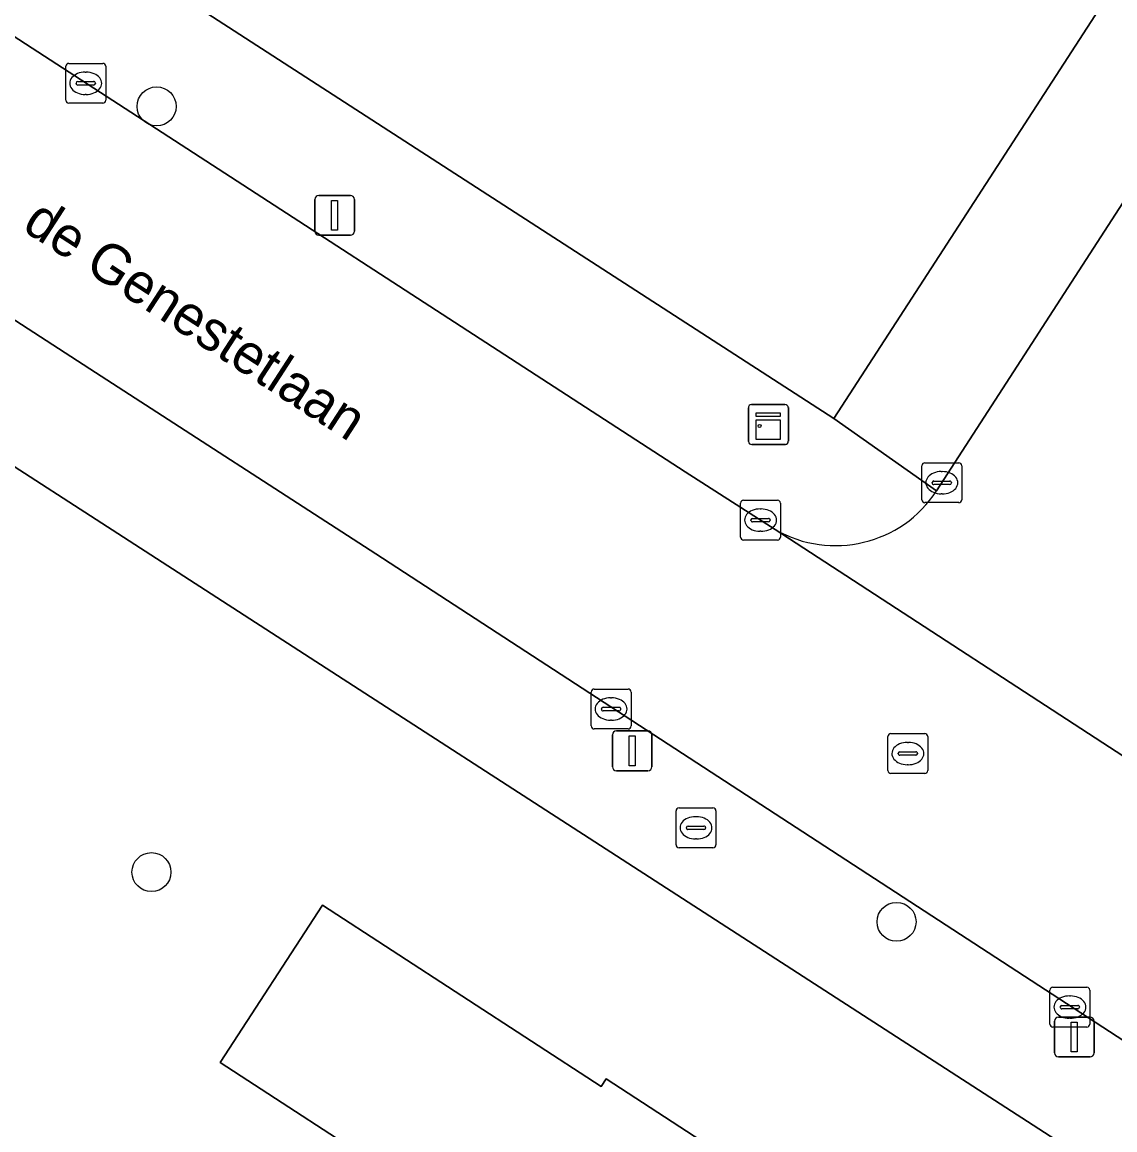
# Model space of a CAD drawing. Extents: x 161139 to 161601, y 381708 to 382245.
# Drawn here: x 161442.02 to 161469.43, y 381969.93 to 381997.72 of the extents above; entities that cross this region are included whole.
import ezdxf

# ---------------------------------------------------------------- set-up
doc = ezdxf.new("R2010")
doc.units = 0
for name, color, linetype in [('IMGEO_Boom', 7, 'Continuous'), ('IMGEO_Brandkraan', 7, 'Continuous'), ('IMGEO_Erf', 7, 'Continuous'), ('IMGEO_Kast', 7, 'Continuous'), ('IMGEO_Kolk', 7, 'Continuous'), ('IMGEO_Lichtmast', 7, 'Continuous'), ('IMGEO_Openbare_ruimte_label', 7, 'Continuous'), ('IMGEO_Pand', 7, 'Continuous'), ('IMGEO_Rijbaan_lokaal_open', 7, 'Continuous'), ('IMGEO_Rioolput', 7, 'Continuous'), ('IMGEO_Voetpad_open', 7, 'Continuous')]:
    doc.layers.add(name, color=color, linetype=linetype)

msp = doc.modelspace()

# ---------------------------------------------------------------- linework, layer by layer
at = {"layer": 'IMGEO_Boom'}
for centre in [(161445.391, 381995.605), (161445.263, 381976.392), (161463.951, 381975.145)]:
    msp.add_circle(centre, 0.489, dxfattribs=at)
at = {"layer": 'IMGEO_Brandkraan'}
for p, q in [((161458.42, 381977.078), (161458.42, 381977.93)), ((161458.495, 381978.004), (161459.347, 381978.004)), ((161459.421, 381977.93), (161459.421, 381977.078)), ((161458.908, 381977.784), (161458.933, 381977.784)), ((161458.679, 381977.498), (161458.679, 381977.51)), ((161459.117, 381977.461), (161458.719, 381977.461)), ((161458.722, 381977.547), (161459.12, 381977.547)), ((161459.163, 381977.51), (161459.163, 381977.498)), ((161458.931, 381977.224), (161458.906, 381977.224)), ((161459.347, 381977.004), (161458.495, 381977.004))]:
    msp.add_line(p, q, dxfattribs=at)
for points in [[(161458.42, 381977.078), (161458.42, 381977.93)], [(161458.495, 381978.004), (161459.347, 381978.004)], [(161459.421, 381977.93), (161459.421, 381977.078)], [(161459.347, 381977.004), (161458.495, 381977.004)]]:
    msp.add_lwpolyline(points, dxfattribs=at)
for centre, radius, start, end in [((161458.497, 381977.928), 0.0765, 91.552, 178.448), ((161458.497, 381977.928), 0.0765, 91.552, 178.448), ((161459.345, 381977.928), 0.0765, 1.552, 88.448), ((161459.345, 381977.928), 0.0765, 1.552, 88.448), ((161458.719, 381977.507), 0.0403, 85.8775, 175.7526), ((161458.716, 381977.497), 0.0366, 178.938, 274.7102), ((161459.12, 381977.504), 0.043, 264.8664, 352.4533), ((161459.124, 381977.509), 0.0386, 1.7309, 96.639), ((161458.497, 381977.08), 0.0765, 181.552, 268.448), ((161458.497, 381977.08), 0.0765, 181.552, 268.448), ((161459.345, 381977.08), 0.0765, 271.552, 358.448), ((161459.345, 381977.08), 0.0765, 271.552, 358.448)]:
    msp.add_arc(centre, radius, start, end, dxfattribs=at)
for centre, major_axis, ratio, start_param, end_param in [((161458.907, 381977.504), (-0.387, 0.002), 0.722429, 4.712389, 7.853982), ((161458.932, 381977.504), (-0.39, 0.002), 0.717154, 1.570796, 4.712389)]:
    msp.add_ellipse(centre, major_axis=major_axis, ratio=ratio, start_param=start_param, end_param=end_param, dxfattribs=at)
at = {"layer": 'IMGEO_Erf'}
for points in [[(161320.525, 382089.631), (161313.623, 382083.997), (161443.483, 382000), (161462.38, 381987.777), (161470.3, 382000), (161498.24, 382043.117), (161359.011, 382133.266)], [(161430.666, 381897.334), (161474.804, 381965.241), (161421.048, 382000)]]:
    msp.add_lwpolyline(points, dxfattribs=at)
msp.add_lwpolyline([(161449.552, 381975.564), (161456.544, 381971.017), (161456.666, 381971.205), (161459.982, 381969.048), (161460.425, 381969.728), (161463.898, 381967.469), (161463.48, 381966.826), (161467.104, 381964.469), (161462.709, 381957.712), (161458.518, 381960.439), (161452.348, 381964.452), (161454.026, 381967.032), (161451.457, 381968.703), (161446.982, 381971.614)], close=True, dxfattribs=at)
at = {"layer": 'IMGEO_Kast'}
for p, q in [((161460.237, 381987.198), (161460.237, 381988.039)), ((161460.237, 381988.039), (161460.237, 381987.198)), ((161460.312, 381988.123), (161461.153, 381988.123)), ((161461.153, 381988.123), (161460.312, 381988.123)), ((161461.237, 381988.048), (161461.237, 381987.207)), ((161461.237, 381987.207), (161461.237, 381988.048)), ((161461.162, 381987.123), (161460.321, 381987.123)), ((161460.321, 381987.123), (161461.162, 381987.123))]:
    msp.add_line(p, q, dxfattribs=at)
for points in [[(161460.432, 381987.913), (161461.032, 381987.913), (161461.032, 381987.828), (161460.432, 381987.828), (161460.432, 381987.913)], [(161460.432, 381987.738), (161461.032, 381987.738), (161461.032, 381987.249), (161460.432, 381987.249), (161460.432, 381987.738)]]:
    msp.add_lwpolyline(points, dxfattribs=at)
msp.add_circle((161460.516, 381987.587), 0.0377, dxfattribs=at)
for centre, start, end in [((161460.315, 381988.045), 92.4484, 184.2845), ((161460.315, 381988.045), 92.4484, 184.2845), ((161461.159, 381988.045), 2.4484, 94.2845), ((161461.159, 381988.045), 2.4484, 94.2845), ((161460.315, 381987.201), 182.4484, 274.2845), ((161460.315, 381987.201), 182.4484, 274.2845), ((161461.159, 381987.201), 272.4484, 4.2845), ((161461.159, 381987.201), 272.4484, 4.2845)]:
    msp.add_arc(centre, 0.0779, start, end, dxfattribs=at)
at = {"layer": 'IMGEO_Kolk'}
for p, q in [((161443.113, 381995.759), (161443.113, 381996.611)), ((161443.188, 381996.685), (161444.04, 381996.685)), ((161444.114, 381996.611), (161444.114, 381995.759)), ((161443.415, 381996.228), (161443.813, 381996.228)), ((161443.601, 381996.465), (161443.626, 381996.465)), ((161443.372, 381996.179), (161443.372, 381996.191)), ((161443.81, 381996.142), (161443.412, 381996.142)), ((161443.856, 381996.191), (161443.856, 381996.179)), ((161444.04, 381995.685), (161443.188, 381995.685)), ((161443.624, 381995.905), (161443.599, 381995.905)), ((161464.586, 381985.737), (161464.586, 381986.589)), ((161464.661, 381986.663), (161465.513, 381986.663)), ((161465.587, 381986.589), (161465.587, 381985.737)), ((161464.888, 381986.206), (161465.286, 381986.206)), ((161465.074, 381986.443), (161465.099, 381986.443)), ((161464.845, 381986.157), (161464.845, 381986.169)), ((161465.283, 381986.12), (161464.885, 381986.12)), ((161465.329, 381986.169), (161465.329, 381986.157)), ((161460.039, 381984.799), (161460.039, 381985.651)), ((161460.114, 381985.725), (161460.966, 381985.725)), ((161461.04, 381985.651), (161461.04, 381984.799)), ((161465.513, 381985.663), (161464.661, 381985.663)), ((161465.097, 381985.883), (161465.072, 381985.883)), ((161460.527, 381985.505), (161460.552, 381985.505)), ((161460.298, 381985.219), (161460.298, 381985.231)), ((161460.736, 381985.182), (161460.338, 381985.182)), ((161460.341, 381985.268), (161460.739, 381985.268)), ((161460.782, 381985.231), (161460.782, 381985.219)), ((161460.55, 381984.945), (161460.525, 381984.945)), ((161460.966, 381984.725), (161460.114, 381984.725)), ((161456.365, 381980.985), (161457.217, 381980.985)), ((161456.29, 381980.059), (161456.29, 381980.911)), ((161456.778, 381980.765), (161456.803, 381980.765)), ((161457.291, 381980.911), (161457.291, 381980.059)), ((161456.549, 381980.479), (161456.549, 381980.491)), ((161456.987, 381980.442), (161456.589, 381980.442)), ((161456.592, 381980.528), (161456.99, 381980.528)), ((161457.033, 381980.491), (161457.033, 381980.479)), ((161456.801, 381980.205), (161456.776, 381980.205)), ((161457.217, 381979.985), (161456.365, 381979.985)), ((161467.798, 381972.58), (161467.798, 381973.432)), ((161467.873, 381973.506), (161468.725, 381973.506)), ((161468.799, 381973.432), (161468.799, 381972.58)), ((161468.286, 381973.286), (161468.311, 381973.286)), ((161468.057, 381973), (161468.057, 381973.012)), ((161468.495, 381972.963), (161468.097, 381972.963)), ((161468.1, 381973.049), (161468.498, 381973.049)), ((161468.541, 381973.012), (161468.541, 381973)), ((161468.309, 381972.726), (161468.284, 381972.726)), ((161468.725, 381972.506), (161467.873, 381972.506))]:
    msp.add_line(p, q, dxfattribs=at)
for points in [[(161443.113, 381995.759), (161443.113, 381996.611)], [(161443.188, 381996.685), (161444.04, 381996.685)], [(161444.114, 381996.611), (161444.114, 381995.759)], [(161444.04, 381995.685), (161443.188, 381995.685)], [(161464.586, 381985.737), (161464.586, 381986.589)], [(161464.661, 381986.663), (161465.513, 381986.663)], [(161465.587, 381986.589), (161465.587, 381985.737)], [(161460.039, 381984.799), (161460.039, 381985.651)], [(161460.114, 381985.725), (161460.966, 381985.725)], [(161461.04, 381985.651), (161461.04, 381984.799)], [(161465.513, 381985.663), (161464.661, 381985.663)], [(161460.966, 381984.725), (161460.114, 381984.725)], [(161456.365, 381980.985), (161457.217, 381980.985)], [(161456.29, 381980.059), (161456.29, 381980.911)], [(161457.291, 381980.911), (161457.291, 381980.059)], [(161457.217, 381979.985), (161456.365, 381979.985)], [(161467.798, 381972.58), (161467.798, 381973.432)], [(161467.873, 381973.506), (161468.725, 381973.506)], [(161468.799, 381973.432), (161468.799, 381972.58)], [(161468.725, 381972.506), (161467.873, 381972.506)]]:
    msp.add_lwpolyline(points, dxfattribs=at)
for centre, radius, start, end in [((161443.19, 381996.609), 0.0765, 91.552, 178.448), ((161443.19, 381996.609), 0.0765, 91.552, 178.448), ((161444.038, 381996.609), 0.0765, 1.552, 88.448), ((161444.038, 381996.609), 0.0765, 1.552, 88.448), ((161443.412, 381996.188), 0.0403, 85.8775, 175.7526), ((161443.817, 381996.19), 0.0386, 1.7309, 96.639), ((161443.409, 381996.178), 0.0366, 178.938, 274.7102), ((161443.813, 381996.185), 0.043, 264.8664, 352.4533), ((161443.19, 381995.761), 0.0765, 181.552, 268.448), ((161443.19, 381995.761), 0.0765, 181.552, 268.448), ((161444.038, 381995.761), 0.0765, 271.552, 358.448), ((161444.038, 381995.761), 0.0765, 271.552, 358.448), ((161464.663, 381986.587), 0.0765, 91.552, 178.448), ((161464.663, 381986.587), 0.0765, 91.552, 178.448), ((161465.511, 381986.587), 0.0765, 1.552, 88.448), ((161465.511, 381986.587), 0.0765, 1.552, 88.448), ((161464.885, 381986.166), 0.0403, 85.8775, 175.7526), ((161465.29, 381986.168), 0.0386, 1.7309, 96.639), ((161464.882, 381986.156), 0.0366, 178.938, 274.7102), ((161465.286, 381986.163), 0.043, 264.8664, 352.4533), ((161460.116, 381985.649), 0.0765, 91.552, 178.448), ((161460.116, 381985.649), 0.0765, 91.552, 178.448), ((161460.964, 381985.649), 0.0765, 1.552, 88.448), ((161460.964, 381985.649), 0.0765, 1.552, 88.448), ((161464.663, 381985.739), 0.0765, 181.552, 268.448), ((161464.663, 381985.739), 0.0765, 181.552, 268.448), ((161465.511, 381985.739), 0.0765, 271.552, 358.448), ((161465.511, 381985.739), 0.0765, 271.552, 358.448), ((161460.338, 381985.228), 0.0403, 85.8775, 175.7526), ((161460.335, 381985.218), 0.0366, 178.938, 274.7102), ((161460.739, 381985.225), 0.043, 264.8664, 352.4533), ((161460.743, 381985.23), 0.0386, 1.7309, 96.639), ((161460.116, 381984.801), 0.0765, 181.552, 268.448), ((161460.116, 381984.801), 0.0765, 181.552, 268.448), ((161460.964, 381984.801), 0.0765, 271.552, 358.448), ((161460.964, 381984.801), 0.0765, 271.552, 358.448), ((161456.367, 381980.909), 0.0765, 91.552, 178.448), ((161456.367, 381980.909), 0.0765, 91.552, 178.448), ((161457.215, 381980.909), 0.0765, 1.552, 88.448), ((161457.215, 381980.909), 0.0765, 1.552, 88.448), ((161456.589, 381980.488), 0.0403, 85.8775, 175.7526), ((161456.586, 381980.478), 0.0366, 178.938, 274.7102), ((161456.99, 381980.485), 0.043, 264.8664, 352.4533), ((161456.994, 381980.49), 0.0386, 1.7309, 96.639), ((161456.367, 381980.061), 0.0765, 181.552, 268.448), ((161456.367, 381980.061), 0.0765, 181.552, 268.448), ((161457.215, 381980.061), 0.0765, 271.552, 358.448), ((161457.215, 381980.061), 0.0765, 271.552, 358.448), ((161467.875, 381973.43), 0.0765, 91.552, 178.448), ((161467.875, 381973.43), 0.0765, 91.552, 178.448), ((161468.723, 381973.43), 0.0765, 1.552, 88.448), ((161468.723, 381973.43), 0.0765, 1.552, 88.448), ((161468.097, 381973.009), 0.0403, 85.8775, 175.7526), ((161468.094, 381972.999), 0.0366, 178.938, 274.7102), ((161468.498, 381973.006), 0.043, 264.8664, 352.4533), ((161468.502, 381973.011), 0.0386, 1.7309, 96.639), ((161467.875, 381972.582), 0.0765, 181.552, 268.448), ((161467.875, 381972.582), 0.0765, 181.552, 268.448), ((161468.723, 381972.582), 0.0765, 271.552, 358.448), ((161468.723, 381972.582), 0.0765, 271.552, 358.448)]:
    msp.add_arc(centre, radius, start, end, dxfattribs=at)
for centre, major_axis, ratio, start_param, end_param in [((161443.6, 381996.185), (-0.387, 0.002), 0.722429, 4.712389, 7.853982), ((161443.625, 381996.185), (-0.39, 0.002), 0.717154, 1.570796, 4.712389), ((161465.073, 381986.163), (-0.387, 0.002), 0.722429, 4.712389, 7.853982), ((161465.098, 381986.163), (-0.39, 0.002), 0.717154, 1.570796, 4.712389), ((161460.526, 381985.225), (-0.387, 0.002), 0.722429, 4.712389, 7.853982), ((161460.551, 381985.225), (-0.39, 0.002), 0.717154, 1.570796, 4.712389), ((161456.777, 381980.485), (-0.387, 0.002), 0.722429, 4.712389, 7.853982), ((161456.802, 381980.485), (-0.39, 0.002), 0.717154, 1.570796, 4.712389), ((161468.285, 381973.006), (-0.387, 0.002), 0.722429, 4.712389, 7.853982), ((161468.31, 381973.006), (-0.39, 0.002), 0.717154, 1.570796, 4.712389)]:
    msp.add_ellipse(centre, major_axis=major_axis, ratio=ratio, start_param=start_param, end_param=end_param, dxfattribs=at)
at = {"layer": 'IMGEO_Lichtmast'}
for p, q in [((161449.361, 381992.472), (161449.361, 381993.272)), ((161449.361, 381993.272), (161449.361, 381992.472)), ((161449.461, 381993.372), (161450.251, 381993.372)), ((161450.251, 381993.372), (161449.461, 381993.372)), ((161450.351, 381993.272), (161450.351, 381992.472)), ((161450.351, 381992.472), (161450.351, 381993.272)), ((161450.251, 381992.372), (161449.461, 381992.372)), ((161449.461, 381992.372), (161450.251, 381992.372)), ((161456.825, 381979.037), (161456.825, 381979.837)), ((161456.825, 381979.837), (161456.825, 381979.037)), ((161456.925, 381979.937), (161457.715, 381979.937)), ((161457.715, 381979.937), (161456.925, 381979.937)), ((161457.815, 381979.837), (161457.815, 381979.037)), ((161457.815, 381979.037), (161457.815, 381979.837)), ((161457.715, 381978.937), (161456.925, 381978.937)), ((161456.925, 381978.937), (161457.715, 381978.937)), ((161467.914, 381971.856), (161467.914, 381972.656)), ((161467.914, 381972.656), (161467.914, 381971.856)), ((161468.014, 381972.756), (161468.804, 381972.756)), ((161468.804, 381972.756), (161468.014, 381972.756)), ((161468.904, 381972.656), (161468.904, 381971.856)), ((161468.904, 381971.856), (161468.904, 381972.656)), ((161468.804, 381971.756), (161468.014, 381971.756)), ((161468.014, 381971.756), (161468.804, 381971.756))]:
    msp.add_line(p, q, dxfattribs=at)
for points in [[(161449.781, 381993.247), (161449.931, 381993.247), (161449.931, 381992.497), (161449.781, 381992.497), (161449.781, 381993.247)], [(161457.245, 381979.812), (161457.395, 381979.812), (161457.395, 381979.062), (161457.245, 381979.062), (161457.245, 381979.812)], [(161468.334, 381972.631), (161468.484, 381972.631), (161468.484, 381971.881), (161468.334, 381971.881), (161468.334, 381972.631)]]:
    msp.add_lwpolyline(points, dxfattribs=at)
for centre, start, end in [((161449.461, 381993.272), 90, 180), ((161449.461, 381993.272), 90, 180), ((161450.251, 381993.272), 0, 90), ((161450.251, 381993.272), 360, 90), ((161449.461, 381992.472), 180, 270), ((161449.461, 381992.472), 180, 270), ((161450.251, 381992.472), 270, 0), ((161450.251, 381992.472), 270, 0), ((161456.925, 381979.837), 90, 180), ((161456.925, 381979.837), 90, 180), ((161457.715, 381979.837), 0, 90), ((161457.715, 381979.837), 360, 90), ((161456.925, 381979.037), 180, 270), ((161456.925, 381979.037), 180, 270), ((161457.715, 381979.037), 270, 0), ((161457.715, 381979.037), 270, 0), ((161468.014, 381972.656), 90, 180), ((161468.014, 381972.656), 90, 180), ((161468.804, 381972.656), 0, 90), ((161468.804, 381972.656), 360, 90), ((161468.014, 381971.856), 180, 270), ((161468.014, 381971.856), 180, 270), ((161468.804, 381971.856), 270, 0), ((161468.804, 381971.856), 270, 0)]:
    msp.add_arc(centre, 0.1, start, end, dxfattribs=at)
at = {"layer": 'IMGEO_Pand'}
msp.add_lwpolyline([(161458.518, 381960.439), (161462.709, 381957.712), (161467.104, 381964.469), (161463.48, 381966.826), (161463.898, 381967.469), (161460.425, 381969.728), (161459.982, 381969.048), (161456.666, 381971.205), (161456.544, 381971.017), (161449.552, 381975.564), (161446.982, 381971.614), (161451.457, 381968.703), (161454.026, 381967.032), (161452.348, 381964.452)], close=True, dxfattribs=at)
at = {"layer": 'IMGEO_Rijbaan_lokaal_open'}
for points in [[(161500.799, 382041.385), (161464.955, 381985.959)], [(161470.897, 381978.482), (161460.91, 381984.988), (161458.647, 381986.439), (161425.551, 382007.922), (161421.741, 382010.379), (161420.042, 382011.494), (161416.852, 382013.552), (161402.927, 382022.535), (161395.928, 382027.083), (161382.572, 382035.748), (161375.585, 382040.285)], [(161388.068, 382025.069), (161398.439, 382018.395), (161402.555, 382015.697), (161408.287, 382012.005), (161423.318, 382002.239), (161430.314, 381997.713), (161443.856, 381988.93), (161450.889, 381984.377), (161471.977, 381970.646), (161480.897, 381964.849), (161484.169, 381969.847), (161479.648, 381972.672), (161478.162, 381973.768), (161471.247, 381978.26)], [(161460.91, 381984.988), (161470.897, 381978.482)]]:
    msp.add_lwpolyline(points, dxfattribs=at)
msp.add_arc((161462.42, 381987.609), 3.025, 240.0575, 326.9393, dxfattribs=at)
at = {"layer": 'IMGEO_Rioolput'}
for p, q in [((161463.809, 381979.867), (161464.661, 381979.867)), ((161463.734, 381978.941), (161463.734, 381979.793)), ((161464.222, 381979.647), (161464.247, 381979.647)), ((161464.735, 381979.793), (161464.735, 381978.941)), ((161463.993, 381979.361), (161463.993, 381979.373)), ((161464.431, 381979.324), (161464.033, 381979.324)), ((161464.036, 381979.41), (161464.434, 381979.41)), ((161464.477, 381979.373), (161464.477, 381979.361)), ((161464.245, 381979.087), (161464.22, 381979.087)), ((161464.661, 381978.867), (161463.809, 381978.867))]:
    msp.add_line(p, q, dxfattribs=at)
for points in [[(161463.809, 381979.867), (161464.661, 381979.867)], [(161463.734, 381978.941), (161463.734, 381979.793)], [(161464.735, 381979.793), (161464.735, 381978.941)], [(161464.661, 381978.867), (161463.809, 381978.867)]]:
    msp.add_lwpolyline(points, dxfattribs=at)
for centre, radius, start, end in [((161463.811, 381979.791), 0.0765, 91.552, 178.448), ((161463.811, 381979.791), 0.0765, 91.552, 178.448), ((161464.659, 381979.791), 0.0765, 1.552, 88.448), ((161464.659, 381979.791), 0.0765, 1.552, 88.448), ((161464.033, 381979.37), 0.0403, 85.8775, 175.7526), ((161464.03, 381979.36), 0.0366, 178.938, 274.7102), ((161464.434, 381979.367), 0.043, 264.8664, 352.4533), ((161464.438, 381979.372), 0.0386, 1.7309, 96.639), ((161463.811, 381978.943), 0.0765, 181.552, 268.448), ((161463.811, 381978.943), 0.0765, 181.552, 268.448), ((161464.659, 381978.943), 0.0765, 271.552, 358.448), ((161464.659, 381978.943), 0.0765, 271.552, 358.448)]:
    msp.add_arc(centre, radius, start, end, dxfattribs=at)
for centre, major_axis, ratio, start_param, end_param in [((161464.221, 381979.367), (-0.387, 0.002), 0.722429, 4.712389, 7.853982), ((161464.246, 381979.367), (-0.39, 0.002), 0.717154, 1.570796, 4.712389)]:
    msp.add_ellipse(centre, major_axis=major_axis, ratio=ratio, start_param=start_param, end_param=end_param, dxfattribs=at)
at = {"layer": 'IMGEO_Voetpad_open'}
for points in [[(161313.623, 382083.997), (161311.536, 382081.664), (161356.674, 382052.498), (161362.411, 382048.813), (161375.585, 382040.285), (161382.572, 382035.748), (161395.928, 382027.083), (161402.927, 382022.535), (161416.852, 382013.552), (161420.042, 382011.494), (161421.741, 382010.379), (161425.551, 382007.922), (161458.647, 381986.439), (161460.91, 381984.988)], [(161464.955, 381985.959), (161462.38, 381987.777), (161443.483, 382000), (161313.623, 382083.997)], [(161306.066, 382074.349), (161421.048, 382000), (161474.804, 381965.241), (161478.068, 381963.057), (161478.909, 381962.515)], [(161481.77, 381964.253), (161480.897, 381964.849), (161471.977, 381970.646), (161450.889, 381984.377), (161443.856, 381988.93), (161430.314, 381997.713), (161423.318, 382002.239), (161408.287, 382012.005), (161402.555, 382015.697), (161398.439, 382018.395)]]:
    msp.add_lwpolyline(points, dxfattribs=at)
msp.add_lwpolyline([(161500.799, 382041.385), (161498.24, 382043.117), (161470.3, 382000), (161462.38, 381987.777), (161464.955, 381985.959)], close=True, dxfattribs=at)
msp.add_arc((161462.42, 381987.609), 3.025, 240.0575, 326.9393, dxfattribs=at)

# ---------------------------------------------------------------- texts
at = {"layer": 'IMGEO_Openbare_ruimte_label'}
msp.add_text('de Genestetlaan', height=1, rotation=327.041, dxfattribs=at).set_placement((161441.986, 381992.521))

doc.saveas('drawing.dxf')
